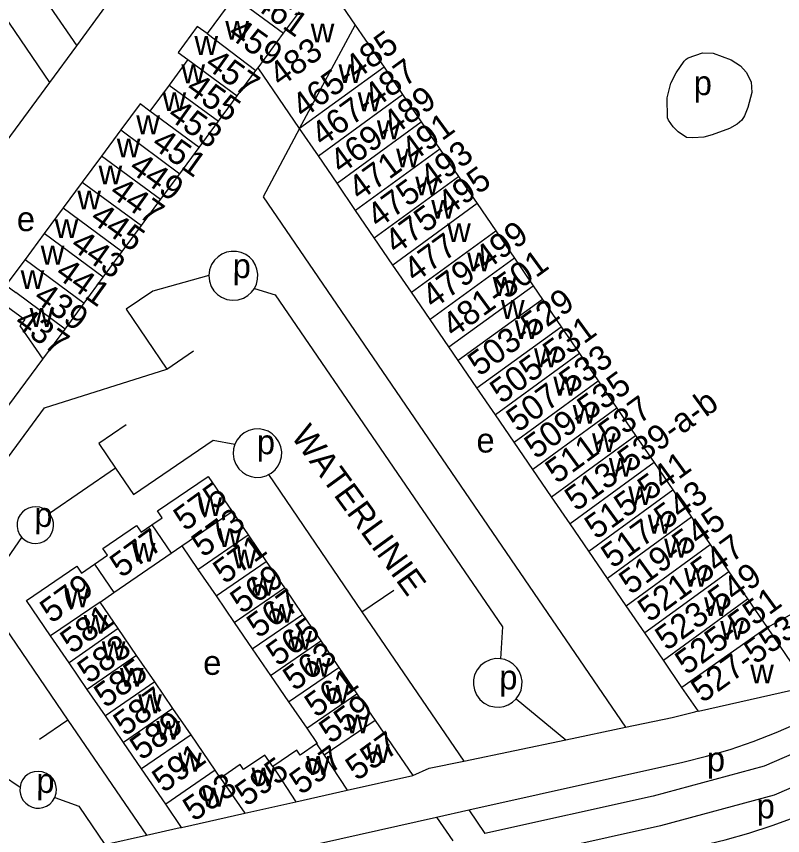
# Model space of a CAD drawing. Extents: x 154320 to 156262, y 382651 to 384180.
# Drawn here: x 155775.5 to 155900.9, y 383197.4 to 383331.4 of the extents above; entities that cross this region are included whole.
import ezdxf

# ---------------------------------------------------------------- set-up
doc = ezdxf.new("R2010")
doc.units = 0
for name, color, linetype in [('BLT_Basislijn', 7, 'Continuous'), ('BLT_Bebouwing', 7, 'Continuous'), ('BLT_Centroide', 7, 'Continuous'), ('BLT_Huisnummer', 7, 'Continuous'), ('BLT_Huisnummer_ tussenligend', 7, 'Continuous'), ('BLT_Huisnummer_reeks', 7, 'Continuous'), ('BLT_Onderdoorgang_en_onderverdeling', 7, 'Continuous'), ('BLT_Onderverdeling_panden', 7, 'Continuous'), ('BLT_Straatnaam', 7, 'Continuous'), ('BLT_Vlakafsluiter', 7, 'Continuous')]:
    doc.layers.add(name, color=color, linetype=linetype)

msp = doc.modelspace()

# ---------------------------------------------------------------- linework, layer by layer
at = {"layer": 'BLT_Basislijn'}
for p, q in [((155772.5, 383345.46), (155785.39, 383326.61)), ((155785.39, 383326.61), (155793.67, 383337.88)), ((155780.99, 383320.63), (155771.12, 383335.1)), ((155780.99, 383320.63), (155785.39, 383326.61)), ((155773.24, 383310.1), (155780.99, 383320.63)), ((155821.86, 383313.07), (155815.88, 383301.89)), ((155815.88, 383301.89), (155875.18, 383215.14)), ((155814.01, 383286.33), (155814.45, 383286.93)), ((155800.12, 383273.73), (155804.49, 383276.69)), ((155791.74, 383257.5), (155780.92, 383250.11)), ((155816.75, 383256.45), (155832.05, 383234.03)), ((155832.05, 383234.03), (155837.25, 383237.58)), ((155772.65, 383232.81), (155783.95, 383216.3)), ((155832.05, 383234.03), (155848.7, 383209.6)), ((155898.32, 383231.44), (155903.07, 383234.06)), ((155857.28, 383219.79), (155865.38, 383213.09)), ((155783.95, 383216.3), (155779.33, 383213.14)), ((155783.95, 383216.3), (155796.82, 383197.47)), ((155865.38, 383213.09), (155875.18, 383215.14)), ((155773.27, 383207.3), (155776.13, 383205.34)), ((155844.27, 383200.42), (155849.52, 383201.59)), ((155849.52, 383201.59), (155852.15, 383197.73)), ((155844.27, 383200.42), (155846.89, 383196.56))]:
    msp.add_line(p, q, dxfattribs=at)
msp.add_lwpolyline([(155881.96, 383318.08), (155882.58, 383320.48), (155883.46, 383322.17), (155884.77, 383324.08), (155885.11, 383324.44), (155885.43, 383324.66), (155887.78, 383325.44), (155889.5, 383325.4), (155892.47, 383324.34), (155893.95, 383323.36), (155894.9, 383322.3), (155895.69, 383320.69), (155895.84, 383318.98), (155895.19, 383316.51), (155894.63, 383315.18), (155894.19, 383314.45), (155893.42, 383313.78), (155892.17, 383313.1), (155889.32, 383312.06), (155887.95, 383311.69), (155886.19, 383311.53), (155885.14, 383311.63), (155883.75, 383312.56), (155882.95, 383313.35), (155882.18, 383314.45), (155882.05, 383314.85)], close=True, dxfattribs=at)
for points in [[(155808.53, 383292.11), (155807.94, 383291.54), (155807.46, 383290.81), (155807.13, 383289.96), (155807.01, 383289.03)], [(155814.45, 383286.93), (155814.79, 383287.64), (155814.99, 383288.43), (155815.02, 383289.26), (155814.88, 383290.08), (155814.59, 383290.83), (155814.18, 383291.47), (155813.67, 383292.01), (155813.05, 383292.45), (155812.32, 383292.79), (155811.51, 383292.97), (155810.68, 383292.98), (155809.88, 383292.83), (155809.15, 383292.53), (155808.53, 383292.11)], [(155807.01, 383289.03), (155797.83, 383286.48), (155793.47, 383283.52), (155800.12, 383273.73)], [(155807.01, 383289.03), (155807.11, 383288.11), (155807.4, 383287.26), (155807.85, 383286.53), (155808.4, 383285.95), (155809.09, 383285.47), (155809.93, 383285.13), (155810.84, 383284.98), (155811.78, 383285.05), (155812.65, 383285.33), (155813.4, 383285.78), (155814.01, 383286.33)], [(155814.45, 383286.93), (155817.88, 383285.85), (155855.02, 383231.54), (155854.69, 383226.34)], [(155753.19, 383230.79), (155780.13, 383267.37), (155800.12, 383273.73)], [(155793.48, 383264.59), (155788.99, 383261.53), (155791.74, 383257.5)], [(155818.69, 383258.63), (155818.88, 383259.37), (155818.92, 383260.19), (155818.79, 383261.03), (155818.47, 383261.83), (155817.99, 383262.54), (155817.39, 383263.12), (155816.71, 383263.54), (155816, 383263.81), (155815.22, 383263.94), (155814.39, 383263.91), (155813.55, 383263.69), (155812.78, 383263.3), (155812.13, 383262.76), (155811.62, 383262.13), (155811.26, 383261.44)], [(155791.74, 383257.5), (155794.68, 383253.2), (155807.74, 383262.12), (155811.26, 383261.44)], [(155811.26, 383261.44), (155811.05, 383260.69), (155810.98, 383259.86), (155811.1, 383259), (155811.41, 383258.17), (155811.89, 383257.43), (155812.51, 383256.84), (155813.19, 383256.4), (155813.91, 383256.13), (155814.71, 383256), (155815.56, 383256.04), (155816.41, 383256.27), (155816.75, 383256.45)], [(155816.75, 383256.45), (155817.2, 383256.69), (155817.86, 383257.25), (155818.36, 383257.92), (155818.69, 383258.63)], [(155776.52, 383250.34), (155776.14, 383249.88), (155775.84, 383249.31), (155775.66, 383248.65), (155775.64, 383247.96), (155775.77, 383247.29), (155776.04, 383246.68), (155776.41, 383246.18)], [(155780.92, 383250.11), (155780.83, 383250.23), (155780.41, 383250.6), (155779.91, 383250.9), (155779.34, 383251.11), (155778.72, 383251.2), (155778.09, 383251.15), (155777.49, 383250.98), (155776.96, 383250.7), (155776.52, 383250.34)], [(155780.99, 383246.34), (155781.29, 383246.82), (155781.51, 383247.37), (155781.62, 383247.98), (155781.6, 383248.61), (155781.44, 383249.22), (155781.18, 383249.77), (155780.92, 383250.11)], [(155772.65, 383232.81), (155772.43, 383236.69), (155773.55, 383241.95), (155776.41, 383246.18)], [(155776.41, 383246.18), (155776.86, 383245.78), (155777.4, 383245.46), (155778.03, 383245.26), (155778.71, 383245.2), (155779.4, 383245.3), (155780.03, 383245.54), (155780.56, 383245.91), (155780.99, 383246.34)], [(155849.52, 383201.59), (155884.54, 383209.44), (155888.43, 383210.39), (155892.27, 383211.51), (155896.05, 383212.8), (155899.78, 383214.25), (155903.45, 383215.85), (155907.03, 383217.63), (155911.13, 383219.89), (155917.48, 383223.85), (155922.14, 383226.87)], [(155854.69, 383226.34), (155853.87, 383226.35), (155853.02, 383226.17), (155852.19, 383225.79), (155851.45, 383225.22), (155850.87, 383224.5), (155850.48, 383223.69), (155850.29, 383222.86), (155850.28, 383222.07), (155850.44, 383221.23), (155850.79, 383220.41), (155851.34, 383219.67), (155852.05, 383219.06), (155852.87, 383218.65), (155853.71, 383218.44), (155854.53, 383218.41)], [(155928.97, 383226.88), (155922.39, 383221.88), (155912.19, 383214.98), (155897.82, 383208.74), (155879.68, 383203.84), (155852.15, 383197.73)], [(155857.28, 383219.79), (155857.75, 383220.46), (155858.07, 383221.19), (155858.22, 383221.94), (155858.24, 383222.67), (155858.11, 383223.42), (155857.83, 383224.17), (155857.39, 383224.86), (155856.81, 383225.45), (155856.14, 383225.9), (155855.41, 383226.2), (155854.69, 383226.34)], [(155932.23, 383223.07), (155925.3, 383217.82), (155914.61, 383210.57), (155899.48, 383204.01), (155880.87, 383198.99), (155855.18, 383193.28)], [(155854.53, 383218.41), (155855.26, 383218.53), (155855.99, 383218.8), (155856.69, 383219.22), (155857.28, 383219.79)], [(155875.18, 383215.14), (155882.82, 383216.74), (155886.48, 383217.64), (155887.02, 383217.8)], [(155858, 383189.14), (155887.6, 383195.77), (155891.49, 383196.72), (155895.34, 383197.79), (155899.14, 383199.05), (155902.9, 383200.42), (155906.6, 383201.93), (155910.24, 383203.58), (155913.82, 383205.38), (155918.19, 383207.8), (155924.24, 383211.67), (155929.2, 383214.78)], [(155840.37, 383207.23), (155843.02, 383208.41), (155848.7, 383209.6)], [(155777.86, 383207.65), (155777.37, 383207.38), (155776.93, 383206.99), (155776.55, 383206.5), (155776.28, 383205.94), (155776.13, 383205.34)], [(155781.82, 383203.66), (155782.03, 383204.32), (155782.08, 383204.98), (155782, 383205.61), (155781.8, 383206.18), (155781.47, 383206.72), (155781, 383207.2), (155780.43, 383207.58), (155779.77, 383207.82), (155779.09, 383207.91), (155778.44, 383207.84), (155777.86, 383207.65)], [(155776.13, 383205.34), (155776.1, 383204.73), (155776.19, 383204.16), (155776.37, 383203.64), (155776.66, 383203.14), (155777.07, 383202.69), (155777.56, 383202.32), (155778.13, 383202.05), (155778.73, 383201.91), (155779.32, 383201.89), (155779.87, 383201.98)], [(155779.87, 383201.98), (155780.44, 383202.21), (155780.99, 383202.57), (155781.46, 383203.06), (155781.82, 383203.66)], [(155781.82, 383203.66), (155785.72, 383202.21), (155790.01, 383195.94)], [(155759.27, 383180.32), (155763.06, 383181.61), (155766.88, 383182.79), (155770.73, 383183.86), (155774.62, 383184.83), (155777.81, 383185.54), (155844.27, 383200.42)], [(155796.82, 383197.47), (155802.34, 383198.72), (155802.56, 383198.74)]]:
    msp.add_lwpolyline(points, dxfattribs=at)
at = {"layer": 'BLT_Bebouwing'}
for p, q in [((155811.17, 383334.61), (155806.72, 383328.6)), ((155828.8, 383333.07), (155830.92, 383329.99)), ((155830.92, 383329.99), (155835.66, 383323.09)), ((155803.58, 383324.35), (155800.51, 383320.19)), ((155811.65, 383318.41), (155814.7, 383322.55)), ((155814.7, 383322.55), (155815.06, 383323.03)), ((155821.86, 383313.07), (155815.06, 383323.03)), ((155835.66, 383323.09), (155838.7, 383318.63)), ((155800.51, 383320.19), (155797.36, 383315.92)), ((155838.7, 383318.63), (155841.75, 383314.17)), ((155808.59, 383314.27), (155811.65, 383318.41)), ((155805.41, 383309.97), (155808.59, 383314.27)), ((155841.75, 383314.17), (155844.8, 383309.71)), ((155792.61, 383312.85), (155789.46, 383308.58)), ((155824.92, 383308.59), (155821.86, 383313.07)), ((155802.24, 383305.69), (155805.41, 383309.97)), ((155844.8, 383309.71), (155847.84, 383305.25)), ((155789.46, 383308.58), (155786.31, 383304.32)), ((155827.97, 383304.13), (155824.92, 383308.59)), ((155799.12, 383301.45), (155802.24, 383305.69)), ((155847.84, 383305.25), (155850.89, 383300.79)), ((155786.31, 383304.32), (155783.19, 383300.1)), ((155831.02, 383299.67), (155827.97, 383304.13)), ((155795.97, 383297.19), (155799.12, 383301.45)), ((155783.19, 383300.1), (155780.07, 383295.88)), ((155850.89, 383300.79), (155853.94, 383296.32)), ((155834.07, 383295.21), (155831.02, 383299.67)), ((155792.84, 383292.96), (155795.97, 383297.19)), ((155780.07, 383295.88), (155776.95, 383291.65)), ((155853.94, 383296.32), (155856.98, 383291.86)), ((155837.12, 383290.75), (155834.07, 383295.21)), ((155789.72, 383288.74), (155792.84, 383292.96)), ((155856.98, 383291.86), (155860.08, 383287.32)), ((155840.17, 383286.29), (155837.12, 383290.75)), ((155786.6, 383284.52), (155789.72, 383288.74)), ((155860.08, 383287.32), (155861.6, 383285.09)), ((155843.22, 383281.83), (155840.17, 383286.29)), ((155861.6, 383285.09), (155864.65, 383280.63)), ((155783.51, 383280.27), (155786.6, 383284.52)), ((155846.27, 383277.37), (155843.22, 383281.83)), ((155779.84, 383275.32), (155783.51, 383280.27)), ((155864.65, 383280.63), (155867.66, 383276.26)), ((155847.8, 383275.14), (155846.27, 383277.37)), ((155867.66, 383276.26), (155870.71, 383271.8)), ((155771.65, 383264.26), (155779.84, 383275.32)), ((155850.85, 383270.68), (155847.8, 383275.14)), ((155870.71, 383271.8), (155873.76, 383267.34)), ((155853.9, 383266.23), (155850.85, 383270.68)), ((155873.76, 383267.34), (155876.81, 383262.88)), ((155856.95, 383261.77), (155853.9, 383266.23)), ((155876.81, 383262.88), (155879.86, 383258.42)), ((155860, 383257.31), (155856.95, 383261.77)), ((155879.86, 383258.42), (155882.91, 383253.96)), ((155863.05, 383252.85), (155860, 383257.31)), ((155806.89, 383256.17), (155810.83, 383250.42)), ((155866.1, 383248.39), (155863.05, 383252.85)), ((155882.91, 383253.96), (155885.96, 383249.5)), ((155810.83, 383250.42), (155813.45, 383246.58)), ((155885.96, 383249.5), (155889.01, 383245.04)), ((155869.15, 383243.93), (155866.1, 383248.39)), ((155813.45, 383246.58), (155816.41, 383242.25)), ((155889.01, 383245.04), (155892.06, 383240.58)), ((155791.49, 383237.17), (155800.85, 383243.59)), ((155800.85, 383243.59), (155802.59, 383244.78)), ((155802.59, 383244.78), (155805.21, 383240.94)), ((155872.2, 383239.47), (155869.15, 383243.93)), ((155816.41, 383242.25), (155819.38, 383237.92)), ((155805.21, 383240.94), (155808.18, 383236.61)), ((155875.25, 383235.01), (155872.2, 383239.47)), ((155892.06, 383240.58), (155895.11, 383236.12)), ((155789.21, 383235.61), (155791.49, 383237.17)), ((155819.38, 383237.92), (155822.34, 383233.59)), ((155781.12, 383230.07), (155777.16, 383235.85)), ((155792.18, 383231.27), (155789.21, 383235.61)), ((155808.18, 383236.61), (155811.15, 383232.28)), ((155895.11, 383236.12), (155898.32, 383231.44)), ((155878.3, 383230.55), (155875.25, 383235.01)), ((155822.34, 383233.59), (155825.31, 383229.25)), ((155811.15, 383232.28), (155814.12, 383227.95)), ((155898.32, 383231.44), (155903.3, 383224.14)), ((155784.15, 383225.65), (155781.12, 383230.07)), ((155795.2, 383226.86), (155792.18, 383231.27)), ((155881.35, 383226.09), (155878.3, 383230.55)), ((155825.31, 383229.25), (155828.27, 383224.92)), ((155814.12, 383227.95), (155817.08, 383223.62)), ((155798.17, 383222.53), (155795.2, 383226.86)), ((155884.4, 383221.64), (155881.35, 383226.09)), ((155787.11, 383221.32), (155784.15, 383225.65)), ((155828.27, 383224.92), (155831.23, 383220.59)), ((155817.08, 383223.62), (155820.05, 383219.29)), ((155801.13, 383218.2), (155798.17, 383222.53)), ((155790.08, 383216.98), (155787.11, 383221.32)), ((155887.02, 383217.8), (155884.4, 383221.64)), ((155904.96, 383221.72), (155887.09, 383217.71)), ((155831.23, 383220.59), (155834.2, 383216.25)), ((155804.1, 383213.86), (155801.13, 383218.2)), ((155820.05, 383219.29), (155823.02, 383214.96)), ((155793.04, 383212.65), (155790.08, 383216.98)), ((155887.09, 383217.71), (155887.02, 383217.8)), ((155834.2, 383216.25), (155840.37, 383207.23)), ((155823.02, 383214.96), (155824.72, 383212.47)), ((155796.01, 383208.32), (155793.04, 383212.65)), ((155824.72, 383212.47), (155824.62, 383212.39)), ((155799.96, 383202.54), (155796.01, 383208.32)), ((155808.93, 383206.82), (155808.06, 383208.09)), ((155829.65, 383204.83), (155840.37, 383207.23)), ((155821.25, 383202.95), (155829.65, 383204.83)), ((155802.56, 383198.74), (155799.96, 383202.54)), ((155812.87, 383201.06), (155821.25, 383202.95)), ((155802.56, 383198.74), (155812.87, 383201.06))]:
    msp.add_line(p, q, dxfattribs=at)
for points in [[(155806.72, 383328.6), (155805.11, 383329.78), (155801.98, 383325.53), (155803.58, 383324.35)], [(155797.36, 383315.92), (155795.76, 383317.11), (155792.61, 383312.85)], [(155776.95, 383291.65), (155773.82, 383287.43), (155775.43, 383286.24)], [(155797.67, 383248.22), (155799.39, 383249.4), (155798.63, 383250.52), (155806.89, 383256.17)], [(155788.31, 383241.82), (155790.43, 383243.27), (155789.67, 383244.38), (155795.19, 383248.16), (155795.95, 383247.04), (155797.67, 383248.22)], [(155777.16, 383235.85), (155785.42, 383241.47), (155786.19, 383240.36), (155788.31, 383241.82)], [(155808.06, 383208.09), (155804.1, 383213.86)], [(155824.62, 383212.39), (155821.97, 383210.58), (155821.41, 383211.4), (155817.45, 383208.69)], [(155817.45, 383208.69), (155816.16, 383210.57), (155812.7, 383208.19), (155812.13, 383209.02), (155808.93, 383206.82)]]:
    msp.add_lwpolyline(points, dxfattribs=at)
at = {"layer": 'BLT_Onderdoorgang_en_onderverdeling'}
for p, q in [((155773.85, 383284.08), (155776.89, 383281.82)), ((155776.89, 383281.82), (155776.08, 383280.8)), ((155776.08, 383280.8), (155779.84, 383275.32))]:
    msp.add_line(p, q, dxfattribs=at)
at = {"layer": 'BLT_Onderverdeling_panden'}
for p, q in [((155811.17, 383334.61), (155819.21, 383328.66)), ((155819.21, 383328.66), (155821.81, 383332.18)), ((155821.86, 383313.07), (155830.92, 383329.99)), ((155806.72, 383328.6), (155814.7, 383322.55)), ((155815.06, 383323.03), (155819.21, 383328.66)), ((155803.58, 383324.35), (155811.65, 383318.41)), ((155835.66, 383323.09), (155821.86, 383313.07)), ((155800.51, 383320.19), (155808.59, 383314.27)), ((155824.92, 383308.59), (155838.7, 383318.63)), ((155805.41, 383309.97), (155797.36, 383315.92)), ((155827.97, 383304.13), (155841.75, 383314.17)), ((155792.61, 383312.85), (155802.24, 383305.69)), ((155844.8, 383309.71), (155831.02, 383299.67)), ((155799.12, 383301.45), (155789.46, 383308.58)), ((155834.07, 383295.21), (155847.84, 383305.25)), ((155786.31, 383304.32), (155795.97, 383297.19)), ((155783.19, 383300.1), (155792.84, 383292.96)), ((155850.89, 383300.79), (155837.12, 383290.75)), ((155789.72, 383288.74), (155780.07, 383295.88)), ((155840.17, 383286.29), (155853.94, 383296.32)), ((155856.98, 383291.86), (155843.22, 383281.83)), ((155776.95, 383291.65), (155786.6, 383284.52)), ((155846.27, 383277.37), (155860.08, 383287.32)), ((155783.51, 383280.27), (155775.43, 383286.24)), ((155861.6, 383285.09), (155847.8, 383275.14)), ((155850.85, 383270.68), (155864.65, 383280.63)), ((155867.66, 383276.26), (155853.9, 383266.23)), ((155856.95, 383261.77), (155870.71, 383271.8)), ((155873.76, 383267.34), (155860, 383257.31)), ((155863.05, 383252.85), (155876.81, 383262.88)), ((155879.86, 383258.42), (155866.1, 383248.39)), ((155869.15, 383243.93), (155882.91, 383253.96)), ((155802.59, 383244.78), (155810.83, 383250.42)), ((155885.96, 383249.5), (155872.2, 383239.47)), ((155797.67, 383248.22), (155800.85, 383243.59)), ((155805.21, 383240.94), (155813.45, 383246.58)), ((155875.25, 383235.01), (155889.01, 383245.04)), ((155808.18, 383236.61), (155816.41, 383242.25)), ((155788.31, 383241.82), (155791.49, 383237.17)), ((155892.06, 383240.58), (155878.3, 383230.55)), ((155811.15, 383232.28), (155819.38, 383237.92)), ((155789.21, 383235.61), (155781.12, 383230.07)), ((155881.35, 383226.09), (155895.11, 383236.12)), ((155814.12, 383227.95), (155822.34, 383233.59)), ((155898.32, 383231.44), (155884.4, 383221.64)), ((155792.18, 383231.27), (155784.15, 383225.65)), ((155817.08, 383223.62), (155825.31, 383229.25)), ((155795.2, 383226.86), (155787.11, 383221.32)), ((155820.05, 383219.29), (155828.27, 383224.92)), ((155798.17, 383222.53), (155790.08, 383216.98)), ((155823.02, 383214.96), (155831.23, 383220.59)), ((155801.13, 383218.2), (155793.04, 383212.65)), ((155834.2, 383216.25), (155825.85, 383210.54)), ((155804.1, 383213.86), (155796.01, 383208.32)), ((155824.62, 383212.39), (155825.85, 383210.54)), ((155825.85, 383210.54), (155829.65, 383204.83)), ((155817.45, 383208.69), (155821.25, 383202.95)), ((155808.06, 383208.09), (155799.96, 383202.54)), ((155808.93, 383206.82), (155812.87, 383201.06))]:
    msp.add_line(p, q, dxfattribs=at)
at = {"layer": 'BLT_Vlakafsluiter'}
for p, q in [((155848.7, 383209.6), (155865.38, 383213.09)), ((155790.01, 383195.94), (155796.82, 383197.47))]:
    msp.add_line(p, q, dxfattribs=at)

# ---------------------------------------------------------------- texts
at = {"layer": 'BLT_Centroide'}
for s, p in [('w', (155809.7, 383327.59)), ('w', (155823.67, 383327.16)), ('w', (155804.65, 383325.13)), ('w', (155802.52, 383320.49)), ('w', (155828.22, 383320.5)), ('p', (155886.32, 383318.54)), ('w', (155799.43, 383315.93)), ('w', (155831.36, 383315.91)), ('w', (155795.14, 383312.14)), ('w', (155834.5, 383311.32)), ('w', (155791.95, 383308.35)), ('w', (155837.64, 383306.73)), ('w', (155788.97, 383303.94)), ('w', (155840.77, 383302.14)), ('w', (155785.5, 383299.84)), ('w', (155843.38, 383298.32)), ('e', (155775.6, 383296.29)), ('w', (155781.79, 383295.16)), ('w', (155845.99, 383294.5)), ('w', (155779.51, 383290.82)), ('w', (155849.26, 383289.71)), ('w', (155776.22, 383286.82)), ('w', (155853.44, 383285.69)), ('w', (155854.79, 383281.94)), ('w', (155777.7, 383280.62)), ('w', (155857.04, 383278.65)), ('w', (155860.2, 383274.03)), ('w', (155863.36, 383269.4)), ('w', (155866.52, 383264.78)), ('e', (155850.78, 383260.07)), ('w', (155869.68, 383260.16)), ('w', (155872.43, 383256.13)), ('w', (155875.61, 383251.47)), ('w', (155805.3, 383249.67)), ('w', (155878.8, 383246.81)), ('w', (155808.52, 383244.59)), ('w', (155794.42, 383242.22)), ('w', (155881.49, 383242.88)), ('w', (155810.9, 383241.11)), ('w', (155884.75, 383238.1)), ('w', (155813.94, 383236.68)), ('w', (155783.55, 383234.77)), ('w', (155888.01, 383233.33)), ('w', (155816.98, 383232.24)), ('w', (155786.53, 383230.43)), ('w', (155890.66, 383229.45)), ('w', (155820.02, 383227.81)), ('w', (155789.5, 383226.09)), ('e', (155806.08, 383223.7)), ('w', (155823.06, 383223.38)), ('w', (155792.47, 383221.76)), ('w', (155895.56, 383222.29)), ('w', (155826.1, 383218.94)), ('w', (155795.45, 383217.42)), ('w', (155829.4, 383214.11)), ('w', (155798.42, 383213.08)), ('w', (155832.71, 383209.28)), ('w', (155801.98, 383207.88)), ('w', (155822.94, 383207.33)), ('p', (155888.47, 383207.92)), ('w', (155813.99, 383205.44)), ('w', (155805.85, 383202.16)), ('p', (155896.61, 383200.23))]:
    msp.add_text(s, height=4, dxfattribs=at).set_placement(p)
for p in [(155810.89, 383288.63), (155814.84, 383259.81), (155778.46, 383247.92), (155854.5, 383221.32), (155778.78, 383204.4)]:
    msp.add_text('p', height=4, rotation=359.5, dxfattribs=at).set_placement(p)
at = {"layer": 'BLT_Huisnummer'}
for s, rotation, p in [('483', 36.0883, (155818.72, 383319.77)), ('457', 324.4158, (155806.15, 383323.16)), ('453', 324.4158, (155800.03, 383314.86)), ('449', 324.4158, (155793.73, 383306.2)), ('445', 324.4158, (155787.37, 383297.96)), ('477', 36.0883, (155840.72, 383287.77)), ('441', 324.4158, (155781.68, 383288.94)), ('437', 324.4158, (155774.99, 383280.9)), ('575', 36.0883, (155803.12, 383247.08)), ('569', 36.0883, (155812.39, 383233.55)), ('579', 36.0883, (155781.27, 383232)), ('565', 36.0883, (155818.28, 383224.96)), ('583', 36.0883, (155787.4, 383222.12)), ('561', 36.0883, (155824.56, 383216.58)), ('587', 36.0883, (155793.27, 383213.53)), ('557', 36.0883, (155831.25, 383206.24)), ('591', 36.0883, (155799.62, 383204.29)), ('597', 36.0883, (155822.08, 383203.95)), ('595', 36.0883, (155813.18, 383202.04)), ('593', 34.4158, (155804.55, 383199.6))]:
    msp.add_text(s, height=4, rotation=rotation, dxfattribs=at).set_placement(p)
at = {"layer": 'BLT_Huisnummer_ tussenligend'}
for s, rotation, p in [('461', 324.4158, (155814.04, 383333.07)), ('459', 324.4158, (155809.91, 383328.21)), ('455', 324.4158, (155803.04, 383319.17)), ('451', 324.4158, (155797.42, 383310.13)), ('447', 324.4158, (155790.53, 383302.2)), ('443', 324.4158, (155784.16, 383293.55)), ('439', 324.4158, (155778.13, 383284.97)), ('573', 36.0883, (155806.06, 383242.8)), ('577', 36.0883, (155792.7, 383239.45)), ('571', 36.0883, (155809.59, 383238.44)), ('567', 36.0883, (155815.1, 383229.57)), ('581', 36.0883, (155784.59, 383227)), ('563', 36.0883, (155821.02, 383220.94)), ('585', 36.0883, (155790.11, 383218.16)), ('559', 36.0883, (155826.93, 383212.31)), ('589', 36.0883, (155795.98, 383209.59))]:
    msp.add_text(s, height=4, rotation=rotation, dxfattribs=at).set_placement(p)
at = {"layer": 'BLT_Huisnummer_reeks'}
for s, p in [('465-485', (155822.45, 383314.62)), ('467-487', (155825.59, 383309.99)), ('469-489', (155828.66, 383305.52)), ('471-491', (155831.68, 383301.15)), ('475-493', (155834.72, 383296.65)), ('475-495', (155837.62, 383292.4)), ('479-499', (155843.72, 383283.45)), ('481-501', (155847.04, 383278.74)), ('503-529', (155851.25, 383272.42)), ('505-531', (155854.88, 383267.92)), ('507-533', (155857.54, 383263.23)), ('509-535', (155860.5, 383258.88)), ('511-537', (155863.94, 383254.84)), ('513-539-a-b', (155867.11, 383250.34)), ('515-541', (155870.37, 383245.74)), ('517-543', (155873.06, 383241)), ('519-545', (155876, 383236.69)), ('521-547', (155879.06, 383232.18)), ('523-549', (155881.9, 383227.53)), ('527-553-555', (155887.77, 383218.99)), ('525-551', (155885.16, 383223.56))]:
    msp.add_text(s, height=4, rotation=36.0883, dxfattribs=at).set_placement(p)
at = {"layer": 'BLT_Straatnaam'}
msp.add_text('WATERLINIE', height=4, rotation=306.0883, dxfattribs=at).set_placement((155820.32, 383262.73))

doc.saveas('drawing.dxf')
